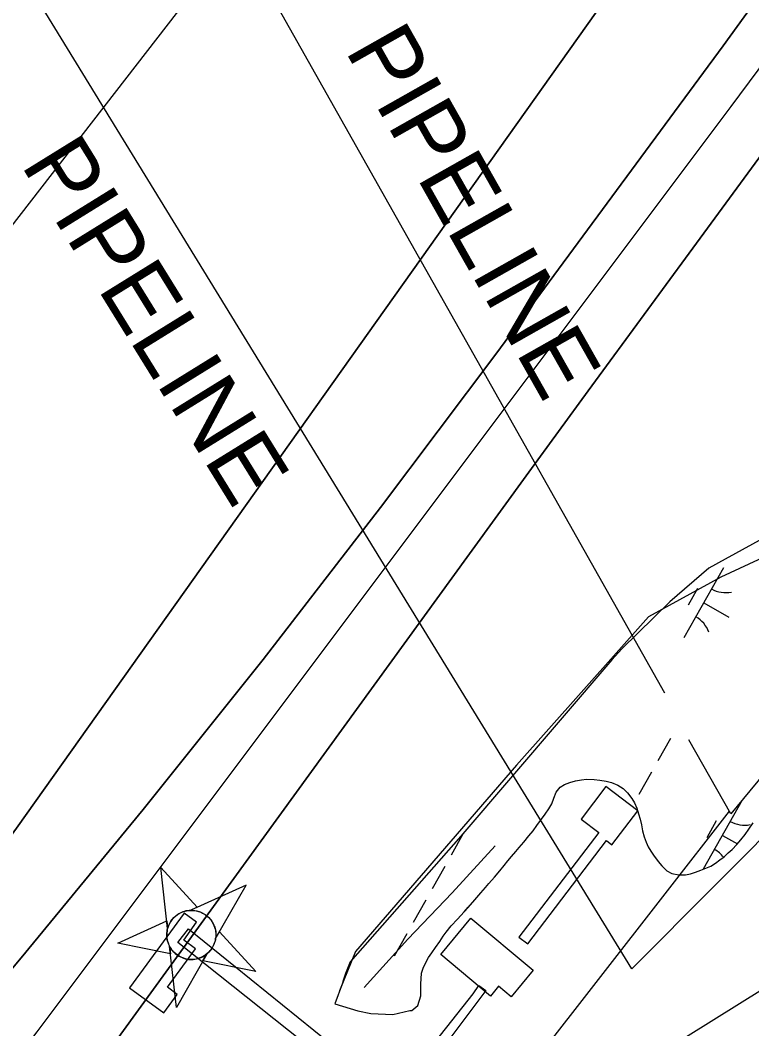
# Model space of a CAD drawing. Extents: x 3913936 to 3933962, y 195330 to 217741.
# Drawn here: x 3923978 to 3924433, y 201638 to 202265 of the extents above; entities that cross this region are included whole.
import ezdxf

# ---------------------------------------------------------------- set-up
doc = ezdxf.new("R2010")
doc.units = 0
for name, color, linetype in [('V-BLDG-OTLN', 7, 'Continuous'), ('V-CHAN-DOCK', 7, 'Continuous'), ('V-CHAN-NAID', 7, 'Continuous'), ('V-RIVR-EDGE', 7, 'Continuous'), ('V-RRAP-FSHR', 7, 'Continuous'), ('V-TOPO-DPTH', 7, 'Continuous'), ('V-TOPO-MINR', 7, 'Continuous'), ('V-TOPO-SHOR', 7, 'Continuous'), ('V-UTIL-IDEN', 7, 'Continuous'), ('V-UTIL-LINE', 7, 'Continuous'), ('V-WETL-SWMP', 7, 'Continuous')]:
    doc.layers.add(name, color=color, linetype=linetype)

msp = doc.modelspace()

# ---------------------------------------------------------------- linework, layer by layer
at = {"layer": 'V-BLDG-OTLN'}
msp.add_lwpolyline([(3924239.34, 201684.12), (3924258.15, 201706.68), (3924296.87, 201674.41), (3924283.12, 201657.9), (3924275.23, 201664.47), (3924270.18, 201658.41)], close=True, dxfattribs=at)
at = {"layer": 'V-CHAN-DOCK'}
for points in [[(3924293.4, 201690.82), (3924342.27, 201754.99), (3924345.7, 201752.38), (3924361.76, 201773.47), (3924341.99, 201788.52), (3924326.6, 201768.3), (3924337.5, 201760), (3924287.98, 201694.95), (3924293.4, 201690.82)], [(3924187.34, 201603.18), (3924076.05, 201691.66), (3924082.7, 201700.08), (3924199.54, 201605.72), (3924195.57, 201600.34), (3924205.64, 201591.72), (3924259.54, 201659.81), (3924263.07, 201664.84), (3924267.32, 201661.91), (3924210.76, 201586.45), (3924392.74, 201440.95), (3924491.85, 201559.54), (3924454.38, 201588.78), (3924492.76, 201637.18), (3924533.44, 201604.75), (3924538.71, 201607.71), (3924673.37, 201504.36)]]:
    msp.add_lwpolyline(points, dxfattribs=at)
msp.add_lwpolyline([(3924069.11, 201695.12), (3924046.06, 201663.43), (3924067.36, 201647.93), (3924075.71, 201659.41), (3924069.65, 201663.82), (3924087.1, 201687.8), (3924079.67, 201693.2), (3924087.69, 201704.22), (3924079.87, 201709.92)], close=True, dxfattribs=at)
at = {"layer": 'V-CHAN-NAID'}
for points in [[(3924069.68, 201700.31), (3924065.48, 201738.32), (3924088, 201713.58), (3924083.63, 201711.61), (3924083.05, 201711.57), (3924081.9, 201711.42), (3924080.99, 201711.24), (3924079.97, 201710.96), (3924079.09, 201710.66), (3924078.23, 201710.31), (3924077.46, 201709.94), (3924076.59, 201709.46), (3924075.78, 201708.94), (3924074.99, 201708.36), (3924074.39, 201707.86), (3924073.76, 201707.28), (3924072.97, 201706.45), (3924072.47, 201705.85), (3924071.86, 201705.03), (3924071.44, 201704.39), (3924070.98, 201703.58), (3924070.6, 201702.82), (3924070.26, 201702.03), (3924069.93, 201701.13)], [(3924099.54, 201694.13), (3924118.48, 201727.36), (3924083.63, 201711.61), (3924084.73, 201711.63), (3924085.64, 201711.58), (3924086.7, 201711.46), (3924087.77, 201711.26), (3924088.43, 201711.1), (3924089.23, 201710.86), (3924089.92, 201710.61), (3924090.66, 201710.3), (3924091.45, 201709.92), (3924092.14, 201709.54), (3924093.02, 201708.99), (3924093.68, 201708.51), (3924094.54, 201707.8), (3924095.26, 201707.12), (3924095.94, 201706.4), (3924096.51, 201705.7), (3924097.03, 201705), (3924097.5, 201704.27), (3924097.99, 201703.38), (3924098.38, 201702.57), (3924098.69, 201701.82), (3924098.95, 201701.11), (3924099.21, 201700.21), (3924099.37, 201699.52), (3924099.56, 201698.42), (3924099.65, 201697.68), (3924099.7, 201696.69), (3924099.69, 201695.7), (3924099.63, 201694.9)], [(3924070.9, 201689.29), (3924071.43, 201684.52), (3924038.67, 201691.3), (3924069.16, 201705.07), (3924069.68, 201700.31), (3924069.48, 201699.46), (3924069.33, 201698.62), (3924069.2, 201697.46), (3924069.16, 201696.48), (3924069.19, 201695.4), (3924069.3, 201694.34), (3924069.46, 201693.36), (3924069.65, 201692.52), (3924069.94, 201691.56), (3924070.25, 201690.7), (3924070.62, 201689.85)], [(3924099.54, 201694.13), (3924101.91, 201698.29), (3924124.43, 201673.56), (3924091.67, 201680.33), (3924094.05, 201684.5), (3924094.69, 201685.04), (3924095.47, 201685.81), (3924096.16, 201686.58), (3924096.8, 201687.4), (3924097.13, 201687.88), (3924097.54, 201688.53), (3924097.96, 201689.28), (3924098.27, 201689.89), (3924098.65, 201690.77), (3924098.88, 201691.42), (3924099.15, 201692.3), (3924099.34, 201693.07), (3924099.45, 201693.6)], [(3924094.05, 201684.5), (3924075.11, 201651.27), (3924070.9, 201689.29), (3924071.33, 201688.52), (3924071.89, 201687.65), (3924072.41, 201686.95), (3924073.08, 201686.15), (3924073.73, 201685.47), (3924074.34, 201684.9), (3924075.13, 201684.25), (3924075.77, 201683.78), (3924076.71, 201683.19), (3924077.61, 201682.7), (3924078.63, 201682.24), (3924079.46, 201681.92), (3924080.55, 201681.59), (3924081.64, 201681.35), (3924082.69, 201681.19), (3924083.48, 201681.12), (3924084.56, 201681.09), (3924085.57, 201681.13), (3924086.61, 201681.25), (3924087.59, 201681.42), (3924088.49, 201681.64), (3924089.56, 201681.98), (3924090.6, 201682.39), (3924091.53, 201682.84), (3924092.48, 201683.38), (3924093.18, 201683.84)]]:
    msp.add_lwpolyline(points, close=True, dxfattribs=at)
msp.add_circle((3924084.43, 201696.36), 15.27, dxfattribs=at)
at = {"layer": 'V-RIVR-EDGE'}
msp.add_lwpolyline([(3925098.63, 202758.93), (3925059.31, 202672.43), (3925011, 202591.54), (3924949.22, 202480.33), (3924880.69, 202352.26), (3924836.88, 202270.25), (3924817.78, 202251.15), (3924794.19, 202225.31), (3924775.09, 202191.61), (3924744.76, 202160.16), (3924732.4, 202146.67), (3924713.3, 202127.58), (3924687.46, 202097.24), (3924658.25, 202064.67), (3924634.66, 202035.46), (3924616.69, 202004), (3924582.99, 201983.78), (3924550.41, 201972.55), (3924474.02, 201946.71), (3924413.35, 201918.62), (3924368.42, 201893.91), (3924286.41, 201801.79), (3924186.42, 201686.08), (3924176.5, 201661.59)], dxfattribs=at)
at = {"layer": 'V-RRAP-FSHR'}
msp.add_lwpolyline([(3924273.22, 201751.8), (3924246.51, 201722.44), (3924218.89, 201693.79), (3924191.72, 201663.72)], dxfattribs=at)
at = {"layer": 'V-TOPO-DPTH'}
for points in [[(3924992.9, 203003.97), (3924555.02, 202345.74), (3924542.66, 202327.33), (3924530.18, 202308.99), (3924517.55, 202290.77), (3924504.81, 202272.62), (3924491.94, 202254.56), (3924479.01, 202236.54), (3924465.99, 202218.59), (3924452.9, 202200.69), (3924405, 202135.5), (3924367.96, 202085.01), (3924330.97, 202034.47), (3924294.08, 201983.86), (3924257.25, 201933.22), (3923922.06, 201471.51), (3923911.22, 201456.61), (3923900.34, 201441.72), (3923889.44, 201426.86), (3923878.5, 201412.02), (3923708.45, 201181.75), (3923640.5, 201090.06), (3923572.36, 200998.52), (3923503.91, 200907.2)], [(3923021.85, 200905.59), (3923325.71, 201305.89), (3923368.53, 201362.16), (3923411.44, 201418.35), (3923454.5, 201474.44), (3923497.65, 201530.45), (3923567.7, 201621.16), (3923575.92, 201631.75), (3923584.16, 201642.31), (3923592.46, 201652.83), (3923600.79, 201663.33), (3923683.12, 201766.64), (3923732.51, 201828.88), (3923781.73, 201891.25), (3923830.7, 201953.81), (3923879.5, 202016.51), (3924180.85, 202405.32), (3924195.7, 202425.15), (3924210.1, 202445.3), (3924223.83, 202465.91), (3924237.1, 202486.83), (3924308.94, 202604.34), (3924356.9, 202684.76), (3924403.67, 202765.84)], [(3923021.85, 200905.59), (3923325.71, 201305.89), (3923368.53, 201362.16), (3923411.44, 201418.35), (3923454.5, 201474.44), (3923497.65, 201530.45), (3923567.7, 201621.16), (3923575.92, 201631.75), (3923584.16, 201642.31), (3923592.46, 201652.83), (3923600.79, 201663.33), (3923683.12, 201766.64), (3923732.51, 201828.88), (3923781.73, 201891.25), (3923830.7, 201953.81), (3923879.5, 202016.51), (3924180.85, 202405.32), (3924195.7, 202425.15), (3924210.1, 202445.3), (3924223.83, 202465.91), (3924237.1, 202486.83), (3924308.94, 202604.34), (3924356.9, 202684.76), (3924403.67, 202765.84)], [(3923130.06, 200754.52), (3923886.98, 201642.64), (3923917.42, 201682.77), (3923947.27, 201723.34), (3923976.75, 201764.19), (3924341.13, 202276.87), (3924356.3, 202298.46), (3924371.3, 202320.16), (3924386.06, 202342.03), (3924400.66, 202364.01), (3924531.02, 202562.63), (3924593.08, 202658.06), (3924654.61, 202753.83)], [(3924654.61, 202753.83), (3924593.08, 202658.06), (3924531.02, 202562.63), (3924400.66, 202364.01), (3924386.06, 202342.03), (3924371.3, 202320.16), (3924356.3, 202298.46), (3924341.13, 202276.87), (3923976.75, 201764.19), (3923947.27, 201723.34), (3923917.42, 201682.77), (3923886.98, 201642.64), (3923130.06, 200754.52)], [(3923353.97, 200902.94), (3923403.94, 200968.88), (3923454.66, 201034.25), (3923505.87, 201099.23), (3923816.26, 201488.45), (3923819.28, 201492.11), (3923822.4, 201495.69), (3923823.98, 201497.46), (3923827.1, 201501.04), (3923828.63, 201502.86), (3923978.81, 201682.18), (3924054.54, 201774.35), (3924129.12, 201867.43), (3924201.96, 201961.88), (3924273.64, 202057.25), (3924414.83, 202248.77), (3924423.58, 202260.78), (3924432.26, 202272.85), (3924440.8, 202285), (3924449.27, 202297.22), (3924696.65, 202658.29), (3924745.15, 202729.8)], [(3924745.15, 202729.8), (3924696.65, 202658.29), (3924449.27, 202297.22), (3924440.8, 202285), (3924432.26, 202272.85), (3924423.58, 202260.78), (3924414.83, 202248.77), (3924273.64, 202057.25), (3924201.96, 201961.88), (3924129.12, 201867.43), (3924054.54, 201774.35), (3923978.81, 201682.18), (3923828.63, 201502.86), (3923827.1, 201501.04), (3923823.98, 201497.46), (3923822.4, 201495.69), (3923819.28, 201492.11), (3923816.26, 201488.45), (3923505.87, 201099.23), (3923454.66, 201034.25), (3923403.94, 200968.88), (3923353.97, 200902.94)]]:
    msp.add_lwpolyline(points, dxfattribs=at)
at = {"layer": 'V-TOPO-MINR'}
for points in [[(3923351.01, 200825.4), (3923855.49, 201471.09), (3923855.91, 201471.62), (3923857.21, 201473.18), (3923858.1, 201474.21), (3923858.54, 201474.73), (3923858.97, 201475.25), (3923902.56, 201527.46), (3923924.57, 201554.26), (3923946.3, 201581.29), (3923967.61, 201608.64), (3923988.63, 201636.23), (3924419.72, 202211.03), (3924436.57, 202233.72), (3924453.27, 202256.52), (3924469.75, 202279.48), (3924486.09, 202302.55), (3924557.12, 202403.88), (3924608.45, 202477.97), (3924659.22, 202552.44), (3924709.16, 202627.47), (3924758.55, 202702.87), (3924974.34, 203036.37)], [(3923503.91, 200907.2), (3923572.36, 200998.52), (3923640.5, 201090.06), (3923708.45, 201181.75), (3923878.5, 201412.02), (3923889.44, 201426.86), (3923900.34, 201441.72), (3923911.22, 201456.61), (3923922.06, 201471.51), (3924257.25, 201933.22), (3924294.08, 201983.86), (3924330.97, 202034.47), (3924367.96, 202085.01), (3924405, 202135.5), (3924452.9, 202200.69), (3924465.99, 202218.59), (3924479.01, 202236.54), (3924491.94, 202254.56), (3924504.81, 202272.62), (3924517.55, 202290.77), (3924530.18, 202308.99), (3924542.66, 202327.33), (3924555.02, 202345.74), (3924992.9, 203003.97)], [(3923021.85, 200905.59), (3923325.71, 201305.89), (3923368.53, 201362.16), (3923411.44, 201418.35), (3923454.5, 201474.44), (3923497.65, 201530.45), (3923567.7, 201621.16), (3923575.92, 201631.75), (3923584.16, 201642.31), (3923592.46, 201652.83), (3923600.79, 201663.33), (3923683.12, 201766.64), (3923732.51, 201828.88), (3923781.73, 201891.25), (3923830.7, 201953.81), (3923879.5, 202016.51), (3924180.85, 202405.32), (3924195.7, 202425.15), (3924210.1, 202445.3), (3924223.83, 202465.91), (3924237.1, 202486.83), (3924308.94, 202604.34), (3924356.9, 202684.76), (3924403.67, 202765.84)], [(3923130.06, 200754.52), (3923886.98, 201642.64), (3923917.42, 201682.77), (3923947.27, 201723.34), (3923976.75, 201764.19), (3924341.13, 202276.87), (3924356.3, 202298.46), (3924371.3, 202320.16), (3924386.06, 202342.03), (3924400.66, 202364.01), (3924531.02, 202562.63), (3924593.08, 202658.06), (3924654.61, 202753.83)], [(3923353.97, 200902.94), (3923403.94, 200968.88), (3923454.66, 201034.25), (3923505.87, 201099.23), (3923816.26, 201488.45), (3923819.28, 201492.11), (3923822.4, 201495.69), (3923823.98, 201497.46), (3923827.1, 201501.04), (3923828.63, 201502.86), (3923978.81, 201682.18), (3924054.54, 201774.35), (3924129.12, 201867.43), (3924201.96, 201961.88), (3924273.64, 202057.25), (3924414.83, 202248.77), (3924423.58, 202260.78), (3924432.26, 202272.85), (3924440.8, 202285), (3924449.27, 202297.22), (3924696.65, 202658.29), (3924745.15, 202729.8)]]:
    msp.add_lwpolyline(points, dxfattribs=at)
at = {"layer": 'V-TOPO-SHOR'}
for points in [[(3924238.75, 201692.26), (3924240.9, 201695.55), (3924242.71, 201697.98), (3924245.9, 201701.97), (3924249.78, 201706.13), (3924254.01, 201710.73), (3924256.51, 201713.51), (3924260.48, 201718.19), (3924264.27, 201722.52), (3924267.2, 201725.82), (3924269.27, 201728.25), (3924272.81, 201732.24), (3924276, 201736.14), (3924278.85, 201739.52), (3924281.09, 201742.3), (3924283.41, 201745.07), (3924286, 201748.28), (3924288.07, 201750.71), (3924290.92, 201754), (3924294.02, 201757.82), (3924296.7, 201761.03), (3924299.02, 201764.32), (3924301.35, 201767.53), (3924304.19, 201771.43), (3924306.43, 201774.64), (3924308.41, 201777.85), (3924309.53, 201781.31), (3924311.17, 201785.04), (3924313.66, 201788.07), (3924316.34, 201789.72), (3924319.63, 201791.03), (3924323.17, 201792.08), (3924326.89, 201792.7), (3924330, 201793.05), (3924334.68, 201792.98), (3924338.23, 201792.47), (3924342.2, 201791.87), (3924345.5, 201791.02), (3924349.39, 201789.47), (3924352.77, 201787.23), (3924355.38, 201784.64), (3924358.07, 201781.1), (3924359.72, 201778.42), (3924361.2, 201775.05), (3924362.33, 201771.68), (3924363.3, 201768.22), (3924364, 201764.68), (3924364.79, 201761.05), (3924365.75, 201757.24), (3924366.97, 201753.96), (3924368.27, 201751.19), (3924369.84, 201748.43), (3924371.58, 201745.84), (3924374.53, 201742.04), (3924376.79, 201739.36), (3924379.82, 201736.17), (3924382.94, 201734.62), (3924387.36, 201733.68), (3924391.51, 201733.78), (3924394.54, 201734.4), (3924397.65, 201735.27), (3924401.02, 201736.49), (3924404.13, 201737.8), (3924407.07, 201739.1), (3924410, 201740.93), (3924412.68, 201743.01), (3924415.45, 201744.92), (3924417.95, 201747.26), (3924420.36, 201749.52), (3924423.3, 201752.47), (3924425.89, 201755.42), (3924428.56, 201758.8), (3924430.8, 201762.01), (3924433.38, 201766.08)], [(3924227.04, 201658.43), (3924226.99, 201658.74), (3924226.98, 201662.29), (3924227.05, 201666.01), (3924227.13, 201669.04), (3924227.47, 201672.59), (3924228.41, 201675.62), (3924229.87, 201678.74), (3924231.85, 201682.38), (3924233.83, 201685.24), (3924236.16, 201688.62), (3924238.75, 201692.26)], [(3924173.5, 201653.6), (3924187.81, 201649.28), (3924195.9, 201647.44), (3924209.57, 201646.86), (3924220.13, 201649.37), (3924221.38, 201649.38), (3924225.1, 201652.49), (3924227.04, 201658.43)]]:
    msp.add_lwpolyline(points, dxfattribs=at)
at = {"layer": 'V-UTIL-LINE'}
for points in [[(3922259.35, 198607.65), (3922481.8, 198996.51), (3922891.23, 199568.37), (3923401.91, 200205.88), (3924391.34, 201632.88), (3925141.51, 202100.49), (3925635.89, 202689.84), (3926060.57, 203224.55), (3926266.36, 203722.12), (3926398.76, 204373.14), (3926759.45, 205211.96), (3927229.53, 206070.79), (3927602.51, 206766.2), (3928031.78, 207586.17)], [(3927650.36, 207012.75), (3925143.73, 202648.17), (3924419.49, 201771.61), (3924393.53, 201817.62)], [(3926953.75, 204871.69), (3926114.53, 203439.18), (3924358.1, 201675.2), (3923230.85, 203513.49)], [(3924378.52, 201846.64), (3923455.57, 203482.72), (3923464.33, 203499.92)], [(3924418.51, 201773.34), (3922973.72, 199916.81)]]:
    msp.add_lwpolyline(points, dxfattribs=at)
at = {"layer": 'V-WETL-SWMP'}
for p, q in [((3924414.97, 201924.45), (3924390.47, 201880.87)), ((3924398.94, 201911.67), (3924393.06, 201901.21)), ((3924402.72, 201902.66), (3924418.41, 201893.84)), ((3924382.03, 201818.47), (3924374.19, 201804.52)), ((3924370.27, 201797.55), (3924362.43, 201783.6)), ((3924426.6, 201779.99), (3924402.5, 201737.11)), ((3924410.57, 201767.2), (3924404.69, 201756.74)), ((3924253.33, 201759.43), (3924245.75, 201745.94)), ((3924414.35, 201758.19), (3924423.71, 201752.94)), ((3924241.83, 201738.97), (3924233.99, 201725.02)), ((3924230.07, 201718.05), (3924222.23, 201704.1)), ((3924218.31, 201697.13), (3924210.47, 201683.18))]:
    msp.add_line(p, q, dxfattribs=at)
for points in [[(3924481.73, 201965.95), (3924416, 201929.76), (3924405.94, 201924.31), (3924381.61, 201903.33), (3924351.87, 201874.2), (3924345.69, 201867.21), (3924251.9, 201757.75), (3924183.19, 201679.72), (3924180.11, 201672.36), (3924178.57, 201667.32), (3924178.3, 201666.39), (3924173.5, 201653.6), (3924187.81, 201649.28), (3924195.89, 201647.44), (3924209.57, 201646.86), (3924220.13, 201649.37), (3924221.38, 201649.38), (3924225.1, 201652.5), (3924227.01, 201658.42), (3924226.99, 201658.74), (3924226.98, 201662.29), (3924227.05, 201666.01), (3924227.13, 201669.04), (3924227.47, 201672.59), (3924228.41, 201675.62), (3924229.87, 201678.74), (3924231.85, 201682.38), (3924233.83, 201685.24), (3924236.16, 201688.62), (3924238.75, 201692.26), (3924240.9, 201695.55), (3924242.71, 201697.98), (3924245.9, 201701.97), (3924249.78, 201706.13), (3924254.01, 201710.73), (3924256.51, 201713.5), (3924260.48, 201718.19), (3924264.27, 201722.52), (3924267.2, 201725.82), (3924269.27, 201728.25), (3924272.81, 201732.24), (3924276, 201736.14), (3924278.85, 201739.52), (3924281.09, 201742.3)], [(3924281.09, 201742.3), (3924283.42, 201745.07), (3924286, 201748.28), (3924288.07, 201750.71), (3924290.92, 201754.01), (3924294.02, 201757.82), (3924296.7, 201761.03), (3924299.02, 201764.32), (3924301.35, 201767.53), (3924304.19, 201771.43), (3924306.43, 201774.64), (3924308.42, 201777.85), (3924309.53, 201781.31), (3924311.16, 201785.04), (3924313.66, 201788.07), (3924316.34, 201789.72), (3924319.63, 201791.03), (3924323.17, 201792.08), (3924326.89, 201792.69), (3924330, 201793.05), (3924334.68, 201792.98), (3924338.22, 201792.47), (3924342.21, 201791.87), (3924345.5, 201791.02), (3924349.39, 201789.47), (3924352.77, 201787.23), (3924355.38, 201784.64), (3924358.07, 201781.1), (3924359.72, 201778.42), (3924361.2, 201775.05), (3924362.33, 201771.68), (3924363.3, 201768.22), (3924364, 201764.68), (3924364.79, 201761.05), (3924365.75, 201757.24), (3924366.97, 201753.96), (3924368.27, 201751.19), (3924369.84, 201748.43), (3924371.58, 201745.84), (3924374.53, 201742.04), (3924376.79, 201739.36), (3924379.82, 201736.17), (3924382.94, 201734.62), (3924387.36, 201733.68), (3924391.51, 201733.78), (3924394.54, 201734.4), (3924397.65, 201735.27), (3924401.02, 201736.49), (3924404.13, 201737.8), (3924407.07, 201739.1), (3924410.01, 201740.93), (3924412.68, 201743.01), (3924415.45, 201744.92), (3924417.95, 201747.27), (3924420.36, 201749.52), (3924423.3, 201752.47), (3924425.89, 201755.42), (3924428.56, 201758.8), (3924430.8, 201762.01), (3924433.38, 201766.08)]]:
    msp.add_lwpolyline(points, dxfattribs=at)
for centre, start, end in [((3924416.47, 201926.62), 239.88608, 281.42974), ((3924389.4, 201878.47), 19.88608, 61.42973), ((3924428.1, 201782.15), 239.88608, 281.42974), ((3924401.02, 201734), 37.20907, 61.42973)]:
    msp.add_arc(centre, 17.62, start, end, dxfattribs=at)

# ---------------------------------------------------------------- texts
at = {"layer": 'V-UTIL-IDEN'}
for rotation, p in [(299.47922, (3924179.52, 202246.1)), (301.76041, (3923978.11, 202174.99))]:
    msp.add_text('PIPELINE', height=42, rotation=rotation, dxfattribs=at).set_placement(p)

doc.saveas('drawing.dxf')
